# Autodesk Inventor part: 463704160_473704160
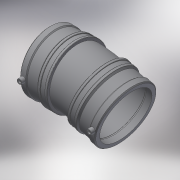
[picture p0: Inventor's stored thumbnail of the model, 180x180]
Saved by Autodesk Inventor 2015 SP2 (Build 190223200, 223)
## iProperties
Created: 2017-06
Part Number: 463704160_473704160
Material: Generic
Description: PLASSON 15° LIGHTFIT ELBOW 160
Document SubType Name: Modeling
Designer: KIM
Mass: 12693.1 g
Surface Area: 10598.3 cm^2
Volume: 12693.1 cm^3
Density: 1 g/cm^3
Appearance: Default
Author: KIM
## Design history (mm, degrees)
derived "46370.ipt"
feature "Solid1::46370.ipt"
tag "TaggingFeature1"
body "Solid1"
other parameters: "d14" = 17.6296, "d19" = 3.52592, "d20" = 168 deg, "d22" = 189.14, "d23" = 193, "d24" = 183.4658, "d25" = 135 deg, "d26" = 106, "d29" = 106, "d43" = 135 deg, "d45" = 10.6, "d47" = 7.95, "d48" = 189.14, "d49" = 193, "d50" = 0.965, "d51" = 94.57, "d52" = 165 deg, "d53" = 265, "d54" = 21.56, "d55" = 88.2, "d56" = 152, "d57" = 58.8, "d58" = 106, "d59" = 15, "d61" = 5 deg, "d63" = 4, "d64" = 14, "d65" = 0, "d67" = 165 deg, "d69" = 176, "d71" = 98, "d72" = 0, "d73" = 98, "d74" = 0, "d75" = 3, "d76" = 0, "L_" = 265, "L_1" = 98, "D_" = 193, "A_" = 106, "d_2" = 12
